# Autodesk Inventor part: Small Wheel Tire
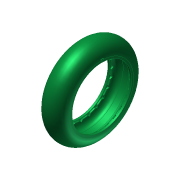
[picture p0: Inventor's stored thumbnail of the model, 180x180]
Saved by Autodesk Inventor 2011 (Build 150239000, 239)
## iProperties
Created: 2010-06
Part Number: Small Wheel Tire
Document SubType Name: Modeling
Designer: kurdi
Density: 1 g/cm^3
Author: kurdi
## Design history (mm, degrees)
sketch "Sketch1"
  geometry: L1 (-9.525, 0)-(9.525, 0); L2 (-9.525, 23.825)-(-6.985, 23.825); L3 (-6.985, 23.825)-(-6.985, 24.13); L4 (6.985, 24.13)-(6.985, 23.825); L5 (6.985, 23.825)-(9.525, 23.825); L6 (9.525, 23.825)-(9.525, 25.4); L7 (-9.525, 25.4)-(-9.525, 23.825); L8 (0, 28.804)-(-2.311, 28.804); L9 (0, 28.804)-(2.311, 28.804); A1 r 9.525 centre (0, 25.4) between (9.525, 25.4) and (-9.525, 25.4); A2 r 4.674 centre (-2.311, 24.13) between (-2.311, 28.804) and (-6.985, 24.13); A3 r 4.674 centre (2.311, 24.13) between (6.985, 24.13) and (2.311, 28.804); 2 further points
  constraints: 18 end point, 6 point on circle, 4 parallel, 4 tangent, 3 centre point, 3 collinear, 2 equal length, 2 perpendicular, 2 vertical alignment, 1 coincident, 1 equal radius, 1 horizontal, 1 midpoint, 1 point on line
  dimensions: "d0" = 9.525 radius of A1; "d1" = 19.05 distance between parallel lines of L6 L7 (derived); "d2" = 2.3114 distance of L8.start L8.end; "d3" = 4.6736 radius of A2; "d4" = 23.8252 distance between parallel lines of L1 L2; "d5" = 28.8036 distance between parallel lines of L1 L8; "d6" = 0.3048 distance of L2.end L3.end; "d7" = 25.4 distance of A1.centre point (0, 0)
revolve "Revolution1" sketch "Sketch1" stored, may be unused: angle "d8" = 90 deg
workplane "Work Plane1"
sketch "Sketch4" dims "d31" = 48.7172
  geometry: L1 (24.359, 0)-(26.36, -1.156); L2 (26.36, -1.156)-(26.36, 1.156); L3 (26.36, 1.156)-(24.359, 0); C1 r 23.825 at (0, 0) reference; 1 further point
  constraints: 6 end point, 2 equal length, 2 horizontal alignment, 1 coincident, 1 vertical, 2 other
  dimensions: "d32" = 2.3114 distance of L1.end L2.end
extrude "Extrusion3" join sketch "Sketch4" distance "d27" = 1.8288; taper "d28" = 0 deg
sketch "Sketch2"
  geometry: L1 (0, 0)-(0, 24.028); L2 (0, 25.355)-(-1.365, 23.99); L3 (0, 25.355)-(1.365, 23.99); L4 (1.892, 23.75)-(0.144, 25.498); L5 (-0.144, 25.498)-(-1.892, 23.75); C1 r 23.825 at (0, 0) reference; C2 r 24.359 at (0, 0); A1 r 24.028 centre (0, 0) between (1.365, 23.99) and (-1.365, 23.99); A2 r 23.825 centre (0, 0) between (1.892, 23.75) and (-1.892, 23.75); A3 r 0.203 centre (0, 25.355) between (0.144, 25.498) and (-0.144, 25.498)
  constraints: 10 end point, 7 point on circle, 4 centre point, 3 perpendicular, 2 tangent, 1 coincident, 1 concentric, 1 point on line, 1 vertical, 2 other
  dimensions: "d10" = 48.0568 diameter of A1; "d11" = 1.9304 distance of L2.start L2.end; "d12" = 0.2032 distance between parallel lines of L5 L2; "d13" = 0.2032 radius of A3; "d23" = 48.7172 diameter of C2
extrude "Extrusion1" cut sketch "Sketch2" stored distance "d17" = 16.002; taper "d18" = 0 deg
sketch "Sketch3"
  geometry: C1 r 24.359 at (0, 0); 1 further point
  constraints: 1 centre point, 1 coincident
  dimensions: "d22" = 48.7172 diameter of C1
extrude "Extrusion2" cut sketch "Sketch3" stored distance "d24" = 16.002; taper "d25" = 0 deg
body "Solid1"
pattern_circular "Circular Pattern1" dims angle "d20" = 360 deg
other parameters: "d30" = 8.001
